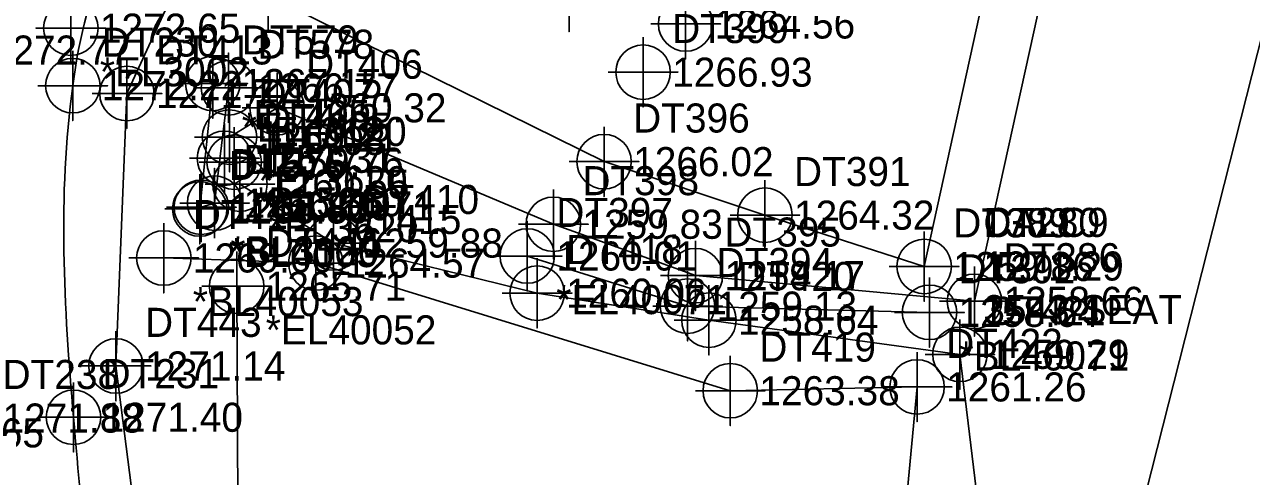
# Model space of a CAD drawing. Extents: x 1391270 to 1392151, y 960049 to 960667.
# Drawn here: x 1391507.1 to 1391612.7, y 960335.6 to 960374.4 of the extents above; entities that cross this region are included whole.
import ezdxf

# ---------------------------------------------------------------- set-up
doc = ezdxf.new("R2010")
doc.units = 0
for name, color, linetype in [('COGO Default Point Elevation', 7, 'Continuous'), ('COGO Default Point Number', 7, 'Continuous'), ('Exist DTM Breakline', 7, 'Continuous'), ('Exist DTM Breakline Cogo Comment', 7, 'Continuous'), ('Exist DTM Breakline Cogo Elevation', 7, 'Continuous'), ('Exist DTM Breakline Cogo Number', 7, 'Continuous'), ('Exist DTM Breakline Cogo Point CELL', 7, 'Continuous'), ('Exist DTM Breakline Underwater', 7, 'Continuous'), ('Exist DTM Breakline Underwater Cogo Comment', 7, 'Continuous'), ('Exist DTM Breakline Underwater Cogo Elevation', 7, 'Continuous'), ('Exist DTM Breakline Underwater Cogo Number', 7, 'Continuous'), ('Exist DTM Breakline Underwater Cogo Point CELL', 7, 'Continuous'), ('Exist DTM Crownline Cogo Elevation', 7, 'Continuous'), ('Exist DTM Crownline Cogo Number', 7, 'Continuous'), ('Exist DTM Regular Point CELL', 7, 'Continuous'), ('Exist DTM Regular Point Cogo Elevation', 7, 'Continuous'), ('Exist DTM Regular Point Cogo Number', 7, 'Continuous'), ('Exist Hydro Stream or Body of Water', 7, 'Continuous'), ('Exist Hydro Stream or Body of Water Cogo Comment', 7, 'Continuous'), ('Exist Hydro Stream or Body of Water Cogo Elevation', 7, 'Continuous'), ('Exist Hydro Stream or Body of Water Cogo Number', 7, 'Continuous'), ('Exist Hydro Stream or Body of Water Cogo Point CELL', 7, 'Continuous'), ('Exist Roads EOP', 7, 'Continuous'), ('Exist Roads EOP Cogo Elevation', 7, 'Continuous'), ('Exist Roads EOP Cogo Number', 7, 'Continuous'), ('Exist Roads EOP Cogo Point CELL', 7, 'Continuous'), ('Exist Roads EOT Cogo Comment', 7, 'Continuous'), ('Exist Roads EOT Cogo Elevation', 7, 'Continuous'), ('Exist Roads EOT Cogo Point CELL', 7, 'Continuous'), ('Exist Structure Minor Head and End Wall', 7, 'Continuous'), ('Exist Structure Minor Head and End Wall Cogo Comment', 7, 'Continuous'), ('Exist Structure Minor Head and End Wall Cogo Elevation', 7, 'Continuous'), ('Exist Structure Minor Head and End Wall Cogo Number', 7, 'Continuous'), ('Exist Structure Minor Head and End Wall Cogo Point CELL', 7, 'Continuous'), ('Exist Structure Minor Pipes CMP 60 Inch Cogo Comment', 7, 'Continuous'), ('Exist Structure Minor Pipes CMP 60 Inch Cogo Elevation', 7, 'Continuous'), ('Exist Structure Minor Pipes CMP 60 Inch Cogo Number', 7, 'Continuous'), ('Exist Structure Minor Pipes CMP 60 Inch Cogo Point CELL', 7, 'Continuous'), ('Exist Utilities Sanitary Sewer Manhole Cogo Comment', 7, 'Continuous'), ('Exist Utilities Sanitary Sewer Manhole Cogo Elevation', 7, 'Continuous'), ('Exist Utilities Sanitary Sewer Manhole Cogo Number', 7, 'Continuous')]:
    doc.layers.add(name, color=color, linetype=linetype)

msp = doc.modelspace()

# ---------------------------------------------------------------- linework, layer by layer
at = {"layer": 'Exist DTM Breakline'}
for p, q in [((1391522.184, 960358.585), (1391523.304, 960369.374)), ((1391525.576, 960313.163), (1391525.367, 960351.939))]:
    msp.add_line(p, q, dxfattribs=at)
for points in [[(1391593.208, 960393.183), (1391584.528, 960353.643), (1391570.827, 960358.056), (1391556.983, 960362.658), (1391528.086, 960376.935), (1391520.577, 960378.658), (1391515.927, 960368.512), (1391514.98, 960345.087), (1391519.249, 960311.75)], [(1391519.093, 960354.373), (1391532.168, 960353.935), (1391567.843, 960342.958), (1391583.917, 960343.284), (1391580.633, 960308.263), (1391572.441, 960270.705), (1391562.786, 960235.192)]]:
    msp.add_lwpolyline(points, dxfattribs=at)
at = {"layer": 'Exist DTM Breakline Cogo Point CELL'}
for points in [[(1391528.086, 960379.935), (1391528.086, 960373.935), (1391528.086, 960376.935), (1391531.086, 960376.935), (1391525.086, 960376.935)], [(1391553.973, 960379.824), (1391553.973, 960373.824), (1391553.973, 960376.824), (1391556.973, 960376.824), (1391550.973, 960376.824)], [(1391523.304, 960372.374), (1391523.304, 960366.374), (1391523.304, 960369.374), (1391526.304, 960369.374), (1391520.304, 960369.374)], [(1391515.927, 960371.512), (1391515.927, 960365.512), (1391515.927, 960368.512), (1391518.927, 960368.512), (1391512.927, 960368.512)], [(1391556.983, 960365.658), (1391556.983, 960359.658), (1391556.983, 960362.658), (1391559.983, 960362.658), (1391553.983, 960362.658)], [(1391522.184, 960361.585), (1391522.184, 960355.585), (1391522.184, 960358.585), (1391525.184, 960358.585), (1391519.184, 960358.585)], [(1391570.827, 960361.056), (1391570.827, 960355.056), (1391570.827, 960358.056), (1391573.827, 960358.056), (1391567.827, 960358.056)], [(1391519.093, 960357.373), (1391519.093, 960351.373), (1391519.093, 960354.373), (1391522.093, 960354.373), (1391516.093, 960354.373)], [(1391532.168, 960356.935), (1391532.168, 960350.935), (1391532.168, 960353.935), (1391535.168, 960353.935), (1391529.168, 960353.935)], [(1391584.528, 960356.643), (1391584.528, 960350.643), (1391584.528, 960353.643), (1391587.528, 960353.643), (1391581.528, 960353.643)], [(1391525.367, 960354.939), (1391525.367, 960348.939), (1391525.367, 960351.939), (1391528.367, 960351.939), (1391522.367, 960351.939)], [(1391514.98, 960348.087), (1391514.98, 960342.087), (1391514.98, 960345.087), (1391517.98, 960345.087), (1391511.98, 960345.087)], [(1391583.917, 960346.284), (1391583.917, 960340.284), (1391583.917, 960343.284), (1391586.917, 960343.284), (1391580.917, 960343.284)], [(1391567.843, 960345.958), (1391567.843, 960339.958), (1391567.843, 960342.958), (1391570.843, 960342.958), (1391564.843, 960342.958)]]:
    msp.add_lwpolyline(points, dxfattribs=at)
for centre in [(1391523.304, 960369.374), (1391515.927, 960368.512), (1391556.983, 960362.658), (1391522.184, 960358.585), (1391570.827, 960358.056), (1391519.093, 960354.373), (1391532.168, 960353.935), (1391584.528, 960353.643), (1391525.367, 960351.939), (1391514.98, 960345.087), (1391567.843, 960342.958), (1391583.917, 960343.284)]:
    msp.add_circle(centre, 2.344, dxfattribs=at)
at = {"layer": 'Exist DTM Breakline Underwater'}
for points in [[(1391637.721, 960501.208), (1391621.569, 960466.64), (1391617.066, 960434.832), (1391615.14, 960379.594), (1391599.785, 960319.127), (1391597.418, 960292.355)], [(1391584.985, 960349.697), (1391564.166, 960350.236), (1391550.373, 960354.541)]]:
    msp.add_lwpolyline(points, dxfattribs=at)
at = {"layer": 'Exist DTM Breakline Underwater Cogo Point CELL'}
for points in [[(1391525.148, 960365.608), (1391525.148, 960359.608), (1391525.148, 960362.608), (1391528.148, 960362.608), (1391522.148, 960362.608)], [(1391550.373, 960357.541), (1391550.373, 960351.541), (1391550.373, 960354.541), (1391553.373, 960354.541), (1391547.373, 960354.541)], [(1391564.166, 960353.236), (1391564.166, 960347.236), (1391564.166, 960350.236), (1391567.166, 960350.236), (1391561.166, 960350.236)], [(1391584.985, 960352.697), (1391584.985, 960346.697), (1391584.985, 960349.697), (1391587.985, 960349.697), (1391581.985, 960349.697)]]:
    msp.add_lwpolyline(points, dxfattribs=at)
for centre in [(1391525.148, 960362.608), (1391550.373, 960354.541), (1391564.166, 960350.236), (1391584.985, 960349.697)]:
    msp.add_circle(centre, 2.344, dxfattribs=at)
at = {"layer": 'Exist DTM Regular Point CELL'}
for points in [[(1391564.002, 960377.494), (1391564.002, 960371.494), (1391564.002, 960374.494), (1391567.002, 960374.494), (1391561.002, 960374.494)], [(1391560.339, 960373.354), (1391560.339, 960367.354), (1391560.339, 960370.354), (1391563.339, 960370.354), (1391557.339, 960370.354)]]:
    msp.add_lwpolyline(points, dxfattribs=at)
for centre in [(1391564.002, 960374.494), (1391560.339, 960370.354)]:
    msp.add_circle(centre, 2.344, dxfattribs=at)
at = {"layer": 'Exist Hydro Stream or Body of Water'}
for points in [[(1391616.765, 960507.42), (1391598.132, 960470.947), (1391598.223, 960437.776), (1391598.007, 960414.172), (1391597.194, 960388.554), (1391588.85, 960350.646), (1391564.84, 960352.852), (1391552.616, 960357.272), (1391528.84, 960367.287), (1391524.75, 960364.767)], [(1391525.646, 960360.725), (1391533.691, 960355.656), (1391551.222, 960351.349), (1391566.005, 960349.028), (1391587.602, 960346.087), (1391590.063, 960325.761), (1391581.908, 960284.337), (1391574.185, 960247.222), (1391569.673, 960235.504)]]:
    msp.add_lwpolyline(points, dxfattribs=at)
at = {"layer": 'Exist Hydro Stream or Body of Water Cogo Point CELL'}
for points in [[(1391525.84, 960367.287), (1391531.84, 960367.287), (1391528.84, 960367.287), (1391528.84, 960364.287), (1391528.84, 960370.287)], [(1391521.75, 960364.767), (1391527.75, 960364.767), (1391524.75, 960364.767), (1391524.75, 960361.767), (1391524.75, 960367.767)], [(1391522.646, 960360.725), (1391528.646, 960360.725), (1391525.646, 960360.725), (1391525.646, 960357.725), (1391525.646, 960363.725)], [(1391549.616, 960357.272), (1391555.616, 960357.272), (1391552.616, 960357.272), (1391552.616, 960354.272), (1391552.616, 960360.272)], [(1391530.691, 960355.656), (1391536.691, 960355.656), (1391533.691, 960355.656), (1391533.691, 960352.656), (1391533.691, 960358.656)], [(1391561.84, 960352.852), (1391567.84, 960352.852), (1391564.84, 960352.852), (1391564.84, 960349.852), (1391564.84, 960355.852)], [(1391548.222, 960351.349), (1391554.222, 960351.349), (1391551.222, 960351.349), (1391551.222, 960348.349), (1391551.222, 960354.349)], [(1391585.85, 960350.646), (1391591.85, 960350.646), (1391588.85, 960350.646), (1391588.85, 960347.646), (1391588.85, 960353.646)], [(1391563.005, 960349.028), (1391569.005, 960349.028), (1391566.005, 960349.028), (1391566.005, 960346.028), (1391566.005, 960352.028)], [(1391584.602, 960346.087), (1391590.602, 960346.087), (1391587.602, 960346.087), (1391587.602, 960343.087), (1391587.602, 960349.087)]]:
    msp.add_lwpolyline(points, dxfattribs=at)
for centre in [(1391528.84, 960367.287), (1391524.75, 960364.767), (1391525.646, 960360.725), (1391552.616, 960357.272), (1391533.691, 960355.656), (1391564.84, 960352.852), (1391551.222, 960351.349), (1391588.85, 960350.646), (1391566.005, 960349.028), (1391587.602, 960346.087)]:
    msp.add_circle(centre, 2.344, dxfattribs=at)
at = {"layer": 'Exist Roads EOP'}
msp.add_spline([(1391553.715, 960387.967), (1391548.413, 960392.843), (1391543.408, 960395.581), (1391535.709, 960395.746), (1391529.074, 960394.424), (1391522.155, 960390.501), (1391514.618, 960381.223), (1391511.262, 960369.19), (1391511.324, 960340.675), (1391514.177, 960312.818)], degree=3, dxfattribs=at)
at = {"layer": 'Exist Roads EOP Cogo Point CELL'}
for points in [[(1391511.262, 960372.19), (1391511.262, 960366.19), (1391511.262, 960369.19), (1391514.262, 960369.19), (1391508.262, 960369.19)], [(1391511.324, 960343.675), (1391511.324, 960337.675), (1391511.324, 960340.675), (1391514.324, 960340.675), (1391508.324, 960340.675)]]:
    msp.add_lwpolyline(points, dxfattribs=at)
for centre in [(1391511.262, 960369.19), (1391511.324, 960340.675)]:
    msp.add_circle(centre, 2.344, dxfattribs=at)
at = {"layer": 'Exist Roads EOT Cogo Point CELL'}
msp.add_lwpolyline([(1391511.094, 960377.137), (1391511.094, 960371.137), (1391511.094, 960374.137), (1391508.094, 960374.137), (1391514.094, 960374.137)], dxfattribs=at)
msp.add_circle((1391511.094, 960374.137), 2.344, dxfattribs=at)
at = {"layer": 'Exist Structure Minor Head and End Wall'}
msp.add_lwpolyline([(1391522.324, 960358.734), (1391523.466, 960359.087), (1391524.665, 960369.001)], dxfattribs=at)
at = {"layer": 'Exist Structure Minor Head and End Wall Cogo Point CELL'}
for points in [[(1391521.665, 960369.001), (1391527.665, 960369.001), (1391524.665, 960369.001), (1391524.665, 960372.001), (1391524.665, 960366.001)], [(1391519.324, 960358.734), (1391525.324, 960358.734), (1391522.324, 960358.734), (1391522.324, 960361.734), (1391522.324, 960355.734)], [(1391520.466, 960359.087), (1391526.466, 960359.087), (1391523.466, 960359.087), (1391523.466, 960362.087), (1391523.466, 960356.087)]]:
    msp.add_lwpolyline(points, dxfattribs=at)
for centre in [(1391524.665, 960369.001), (1391522.324, 960358.734), (1391523.466, 960359.087)]:
    msp.add_circle(centre, 2.344, dxfattribs=at)
at = {"layer": 'Exist Structure Minor Pipes CMP 60 Inch Cogo Point CELL'}
msp.add_lwpolyline([(1391524.311, 960365.945), (1391524.311, 960359.945), (1391524.311, 960362.945), (1391527.311, 960362.945), (1391521.311, 960362.945)], dxfattribs=at)
msp.add_circle((1391524.311, 960362.945), 2.344, dxfattribs=at)

# ---------------------------------------------------------------- texts
at = {"layer": 'COGO Default Point Elevation'}
msp.add_text('1271.29', height=2.5, dxfattribs=at).set_placement((1391589.618, 960352.432))
at = {"layer": 'COGO Default Point Number'}
msp.add_text('CALC9', height=2.5, dxfattribs=at).set_placement((1391589.618, 960356.182))
at = {"layer": 'Exist DTM Breakline Cogo Comment'}
for s, p in [('*EL4005', (1391525.804, 960364.374)), ('*BL4005', (1391524.684, 960353.585)), ('*BL40053', (1391521.593, 960349.373)), ('*EL40052', (1391527.867, 960346.939))]:
    msp.add_text(s, height=2.5, dxfattribs=at).set_placement(p)
at = {"layer": 'Exist DTM Breakline Cogo Elevation'}
for s, p in [('1267.15', (1391525.804, 960368.124)), ('1271.77', (1391518.427, 960367.262)), ('1266.02', (1391559.483, 960361.408)), ('1266.80', (1391524.684, 960357.335)), ('1264.32', (1391573.327, 960356.806)), ('1269.00', (1391521.593, 960353.123)), ('1264.57', (1391534.668, 960352.685)), ('1259.86', (1391587.028, 960352.393)), ('1265.71', (1391527.867, 960350.689)), ('1271.14', (1391517.48, 960343.837)), ('1263.38', (1391570.343, 960341.708)), ('1261.26', (1391586.417, 960342.034))]:
    msp.add_text(s, height=2.5, dxfattribs=at).set_placement(p)
at = {"layer": 'Exist DTM Breakline Cogo Number'}
for s, p in [('DT579', (1391525.804, 960371.874)), ('DT413', (1391518.427, 960371.012)), ('DT396', (1391559.483, 960365.158)), ('DT576', (1391524.684, 960361.085)), ('DT391', (1391573.327, 960360.556)), ('DT414', (1391521.593, 960356.873)), ('DT415', (1391534.668, 960356.435)), ('DT389', (1391587.028, 960356.143)), ('DT446', (1391527.867, 960354.439)), ('DT443', (1391517.48, 960347.587)), ('DT419', (1391570.343, 960345.458)), ('DT422', (1391586.417, 960345.784))]:
    msp.add_text(s, height=2.5, dxfattribs=at).set_placement(p)
at = {"layer": 'Exist DTM Breakline Underwater Cogo Comment'}
for s, p in [('*EL40071', (1391527.648, 960357.608)), ('*EL40071', (1391552.873, 960349.541)), ('*BL40071', (1391587.485, 960344.697))]:
    msp.add_text(s, height=2.5, dxfattribs=at).set_placement(p)
at = {"layer": 'Exist DTM Breakline Underwater Cogo Elevation'}
for s, p in [('1259.76', (1391527.648, 960361.358)), ('1260.01', (1391552.873, 960353.291)), ('1259.13', (1391566.666, 960348.986)), ('1258.64', (1391587.485, 960348.447))]:
    msp.add_text(s, height=2.5, dxfattribs=at).set_placement(p)
at = {"layer": 'Exist DTM Breakline Underwater Cogo Number'}
for s, p in [('DT403', (1391527.648, 960365.108)), ('DT397', (1391552.873, 960357.041)), ('DT394', (1391566.666, 960352.736)), ('DT392', (1391587.485, 960352.197))]:
    msp.add_text(s, height=2.5, dxfattribs=at).set_placement(p)
at = {"layer": 'Exist DTM Crownline Cogo Elevation'}
for s, p in [('1272.77', (1391504.201, 960371.002)), ('1271.88', (1391505.217, 960339.358))]:
    msp.add_text(s, height=2.5, dxfattribs=at).set_placement(p)
at = {"layer": 'Exist DTM Crownline Cogo Number'}
msp.add_text('DT238', height=2.5, dxfattribs=at).set_placement((1391505.217, 960343.108))
at = {"layer": 'Exist DTM Regular Point Cogo Elevation'}
for s, p in [('1264.56', (1391566.502, 960373.244)), ('1266.93', (1391562.839, 960369.104))]:
    msp.add_text(s, height=2.5, dxfattribs=at).set_placement(p)
at = {"layer": 'Exist DTM Regular Point Cogo Number'}
msp.add_text('DT399', height=2.5, dxfattribs=at).set_placement((1391562.839, 960372.854))
at = {"layer": 'Exist Hydro Stream or Body of Water Cogo Comment'}
for s, p in [('*EL3620', (1391527.25, 960359.767)), ('*BL3620', (1391528.146, 960355.725))]:
    msp.add_text(s, height=2.5, dxfattribs=at).set_placement(p)
at = {"layer": 'Exist Hydro Stream or Body of Water Cogo Elevation'}
for s, p in [('1260.32', (1391531.34, 960366.037)), ('1260.21', (1391527.25, 960363.517)), ('1260.55', (1391528.146, 960359.475)), ('1259.83', (1391555.116, 960356.022)), ('1259.88', (1391536.191, 960354.406)), ('1259.17', (1391567.34, 960351.602)), ('1260.06', (1391553.722, 960350.099)), ('1258.66', (1391591.35, 960349.396)), ('1258.64', (1391568.505, 960347.778)), ('1259.29', (1391590.102, 960344.837))]:
    msp.add_text(s, height=2.5, dxfattribs=at).set_placement(p)
at = {"layer": 'Exist Hydro Stream or Body of Water Cogo Number'}
for s, p in [('DT406', (1391531.34, 960369.787)), ('DT407', (1391527.25, 960367.267)), ('DT408', (1391528.146, 960363.225)), ('DT398', (1391555.116, 960359.772)), ('DT410', (1391536.191, 960358.156)), ('DT395', (1391567.34, 960355.352)), ('DT418', (1391553.722, 960353.849)), ('DT386', (1391591.35, 960353.146)), ('DT420', (1391568.505, 960351.528)), ('DT421', (1391590.102, 960348.587))]:
    msp.add_text(s, height=2.5, dxfattribs=at).set_placement(p)
at = {"layer": 'Exist Roads EOP Cogo Elevation'}
for s, p in [('1272.22', (1391513.762, 960367.94)), ('1271.40', (1391513.824, 960339.425)), ('1271.65', (1391496.699, 960338.083))]:
    msp.add_text(s, height=2.5, dxfattribs=at).set_placement(p)
at = {"layer": 'Exist Roads EOP Cogo Number'}
for s, p in [('DT230', (1391513.762, 960371.69)), ('DT231', (1391513.824, 960343.175))]:
    msp.add_text(s, height=2.5, dxfattribs=at).set_placement(p)
at = {"layer": 'Exist Roads EOT Cogo Comment'}
msp.add_text('*EL3002', height=2.5, dxfattribs=at).set_placement((1391513.594, 960369.137))
at = {"layer": 'Exist Roads EOT Cogo Elevation'}
msp.add_text('1272.65', height=2.5, dxfattribs=at).set_placement((1391513.594, 960372.887))
at = {"layer": 'Exist Structure Minor Head and End Wall Cogo Comment'}
for s, p in [('*EL3120', (1391527.165, 960364.001)), ('*BL3120', (1391524.824, 960353.734))]:
    msp.add_text(s, height=2.5, dxfattribs=at).set_placement(p)
at = {"layer": 'Exist Structure Minor Head and End Wall Cogo Elevation'}
for s, p in [('1266.77', (1391527.165, 960367.751)), ('1266.81', (1391524.824, 960357.484)), ('1266.56', (1391525.966, 960357.837))]:
    msp.add_text(s, height=2.5, dxfattribs=at).set_placement(p)
at = {"layer": 'Exist Structure Minor Head and End Wall Cogo Number'}
for s, p in [('DT578', (1391527.165, 960371.501)), ('DT575', (1391524.824, 960361.234)), ('DT577', (1391525.966, 960361.587))]:
    msp.add_text(s, height=2.5, dxfattribs=at).set_placement(p)
at = {"layer": 'Exist Structure Minor Pipes CMP 60 Inch Cogo Comment'}
msp.add_text('*BL5260', height=2.5, dxfattribs=at).set_placement((1391526.811, 960357.945))
at = {"layer": 'Exist Structure Minor Pipes CMP 60 Inch Cogo Elevation'}
msp.add_text('1261.31', height=2.5, dxfattribs=at).set_placement((1391526.811, 960361.695))
at = {"layer": 'Exist Structure Minor Pipes CMP 60 Inch Cogo Number'}
msp.add_text('DT405', height=2.5, dxfattribs=at).set_placement((1391526.811, 960365.445))
at = {"layer": 'Exist Utilities Sanitary Sewer Manhole Cogo Comment'}
msp.add_text('3543 SEAT', height=2.5, dxfattribs=at).set_placement((1391589.618, 960348.682))
at = {"layer": 'Exist Utilities Sanitary Sewer Manhole Cogo Elevation'}
msp.add_text('1271.29', height=2.5, dxfattribs=at).set_placement((1391589.618, 960352.432))
at = {"layer": 'Exist Utilities Sanitary Sewer Manhole Cogo Number'}
msp.add_text('DT280', height=2.5, dxfattribs=at).set_placement((1391589.618, 960356.182))

doc.saveas('drawing.dxf')
